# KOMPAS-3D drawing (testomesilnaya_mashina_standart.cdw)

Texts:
  ОУП-02068108-260601-96-2010
  Тестомесильная машина "Стандарт"
  Игорь
  Тестомесильная машина
  "Стандарт"
  Саранов И.А.
  Рязанов А.Н.
  УП-02068108-260601-2010-
Dimensions and other numbers on the sheet: 1689; 1222; 11; 12; 13; 6; 4; 1; 10; 2; 3; 5; 9; 8; 7; 0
